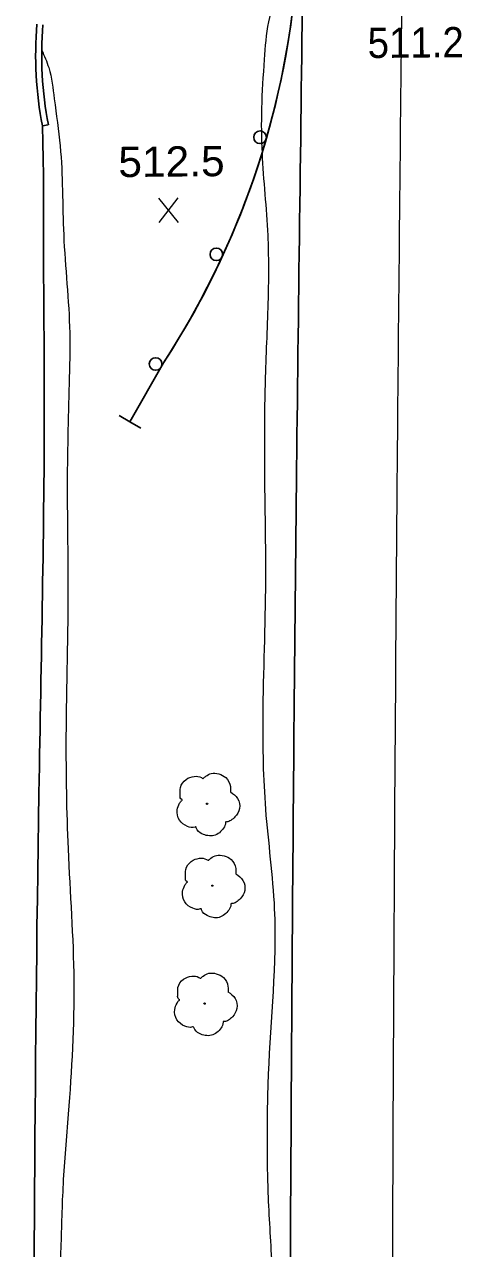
# Model space of a CAD drawing. Extents: x 2362213 to 2366494, y 6968794 to 6978110.
# Drawn here: x 2364395.3 to 2364467.4, y 6971522.8 to 6971717.1 of the extents above; entities that cross this region are included whole.
import ezdxf

# ---------------------------------------------------------------- set-up
doc = ezdxf.new("R2010")
doc.units = 0
doc.header["$LTSCALE"] = 1.9
for name, color, linetype, lineweight in [('2', 7, 'Continuous', 25), ('29', 7, 'Continuous', 13), ('31', 7, 'Continuous', 25), ('35', 7, 'Continuous', 13), ('4', 7, 'Continuous', 25), ('62', 7, 'Continuous', 13)]:
    doc.layers.add(name, color=color, linetype=linetype, lineweight=lineweight)

msp = doc.modelspace()

# ---------------------------------------------------------------- linework, layer by layer
at = {"layer": '2'}
msp.add_line((2364399.119, 6971701.216), (2364398.181, 6971701.037), dxfattribs=at)
for radius in [59.338, 58.378]:
    msp.add_arc((2364456.449, 6971712.252), radius, 175.22755, 190.89519, dxfattribs=at)
for points in [[(2364439.468, 6971722.531), (2364438.425, 6971638.877), (2364437.337, 6971472.728), (2364437.359, 6971266.609), (2364437.925, 6971121.118), (2364438.141, 6971076.417)], [(2364398.181, 6971701.037), (2364398.337, 6971694.068), (2364398.348, 6971685.648), (2364398.475, 6971661.798), (2364397.7, 6971599.308), (2364396.842, 6971464.683), (2364397.471, 6971351.284), (2364398.192, 6971207.384), (2364398.062, 6971077.095)]]:
    msp.add_spline(points, degree=3, dxfattribs=at)
at = {"layer": '29'}
for centre in [(2364424.307, 6971593.42), (2364425.141, 6971580.418), (2364423.909, 6971561.695)]:
    msp.add_circle(centre, 0.1, dxfattribs=at)
for points in [[(2364420.341, 6971593.993), (2364420.361, 6971594.003), (2364420.281, 6971594.072), (2364420.045, 6971594.7), (2364420.082, 6971595.981), (2364420.97, 6971597.279), (2364422.275, 6971597.762), (2364423.397, 6971597.572), (2364423.629, 6971597.444), (2364423.699, 6971597.445), (2364423.748, 6971597.486), (2364424.095, 6971597.779), (2364424.961, 6971598.227), (2364426.172, 6971598.159), (2364427.288, 6971597.569), (2364428.021, 6971596.146), (2364428.029, 6971595.286)], [(2364428.019, 6971595.306), (2364429.159, 6971594.247), (2364429.444, 6971592.659), (2364428.737, 6971591.332), (2364428.082, 6971590.786), (2364427.414, 6971590.569), (2364427.264, 6971590.558), (2364427.245, 6971590.448), (2364426.924, 6971589.544), (2364425.385, 6971588.38), (2364423.492, 6971588.662), (2364422.593, 6971589.603), (2364422.522, 6971589.733), (2364422.402, 6971589.711), (2364421.191, 6971589.83), (2364419.921, 6971590.828), (2364419.576, 6971592.465), (2364419.946, 6971593.489), (2364420.272, 6971593.932), (2364420.341, 6971593.983)], [(2364421.175, 6971580.99), (2364421.195, 6971581.001), (2364421.114, 6971581.07), (2364420.878, 6971581.698), (2364420.916, 6971582.978), (2364421.804, 6971584.276), (2364423.109, 6971584.759), (2364424.231, 6971584.57), (2364424.462, 6971584.442), (2364424.532, 6971584.442), (2364424.582, 6971584.483), (2364424.929, 6971584.776), (2364425.795, 6971585.225), (2364427.006, 6971585.156), (2364428.121, 6971584.567), (2364428.855, 6971583.144), (2364428.863, 6971582.284)], [(2364428.853, 6971582.304), (2364429.993, 6971581.244), (2364430.278, 6971579.657), (2364429.571, 6971578.33), (2364428.916, 6971577.784), (2364428.248, 6971577.568), (2364428.098, 6971577.556), (2364428.079, 6971577.446), (2364427.758, 6971576.543), (2364426.219, 6971575.378), (2364424.326, 6971575.66), (2364423.427, 6971576.602), (2364423.356, 6971576.731), (2364423.236, 6971576.71), (2364422.025, 6971576.828), (2364420.755, 6971577.826), (2364420.41, 6971579.463), (2364420.78, 6971580.487), (2364421.106, 6971580.93), (2364421.175, 6971580.98)], [(2364419.943, 6971562.268), (2364419.963, 6971562.278), (2364419.883, 6971562.347), (2364419.647, 6971562.975), (2364419.684, 6971564.254), (2364420.572, 6971565.553), (2364421.878, 6971566.035), (2364422.999, 6971565.846), (2364423.231, 6971565.718), (2364423.301, 6971565.719), (2364423.35, 6971565.759), (2364423.697, 6971566.053), (2364424.563, 6971566.501), (2364425.774, 6971566.432), (2364426.89, 6971565.843), (2364427.623, 6971564.42), (2364427.631, 6971563.561)], [(2364427.621, 6971563.581), (2364428.761, 6971562.522), (2364429.046, 6971560.934), (2364428.339, 6971559.608), (2364427.684, 6971559.061), (2364427.016, 6971558.845), (2364426.866, 6971558.834), (2364426.847, 6971558.723), (2364426.526, 6971557.82), (2364424.987, 6971556.656), (2364423.094, 6971556.938), (2364422.195, 6971557.879), (2364422.124, 6971558.008), (2364422.004, 6971557.987), (2364420.793, 6971558.106), (2364419.523, 6971559.104), (2364419.178, 6971560.74), (2364419.548, 6971561.764), (2364419.874, 6971562.207), (2364419.943, 6971562.258)]]:
    msp.add_spline(points, degree=3, dxfattribs=at)
at = {"layer": '31', "lineweight": 13}
for p, q in [((2364419.778, 6971685.722), (2364416.661, 6971689.572)), ((2364416.698, 6971685.692), (2364419.741, 6971689.602))]:
    msp.add_line(p, q, dxfattribs=at)
at = {"layer": '35'}
for points in [[(2364439.994, 6971733.486), (2364438.868, 6971733.036), (2364438.147, 6971731.039), (2364437.254, 6971727.13), (2364435.654, 6971722.935), (2364434.055, 6971717.589), (2364433.372, 6971711.592), (2364432.946, 6971703.848), (2364433.023, 6971696.738), (2364433.928, 6971683.656), (2364433.983, 6971673.697), (2364433.542, 6971661.142), (2364433.443, 6971643.22), (2364433.57, 6971628.801), (2364433.146, 6971607.206), (2364433.575, 6971592.568), (2364434.976, 6971576.722), (2364434.016, 6971550.531), (2364433.824, 6971541.278), (2364433.965, 6971531.67), (2364434.542, 6971520.444), (2364434.682, 6971512.086), (2364434.675, 6971506.476), (2364435.314, 6971502.38), (2364436.137, 6971497.868), (2364436.783, 6971490.985), (2364437.739, 6971484.064), (2364438.525, 6971479.27), (2364439.8, 6971472.402), (2364440.687, 6971465.411), (2364441.495, 6971461.388), (2364443.097, 6971457.012), (2364444.712, 6971452.268), (2364445.855, 6971447.699), (2364447.271, 6971444.003), (2364449.509, 6971437.943), (2364450.884, 6971434.246), (2364453.185, 6971427.897), (2364454.981, 6971422.025), (2364456.956, 6971413.122), (2364458.617, 6971405.588), (2364460.577, 6971396.157), (2364461.604, 6971390.206), (2364462.553, 6971379.734), (2364463.261, 6971367.35), (2364463.76, 6971358.005), (2364464.421, 6971351.682), (2364465.168, 6971338.327), (2364465.763, 6971318.912), (2364466.44, 6971301.388), (2364467.187, 6971290.084), (2364468.006, 6971276.621), (2364468.769, 6971265.798), (2364469.742, 6971250.727), (2364469.962, 6971234.958), (2364470.265, 6971224.151), (2364470.975, 6971209.477), (2364470.852, 6971201.435), (2364471.097, 6971179.917), (2364471.587, 6971168.311), (2364471.9, 6971157.543), (2364471.893, 6971141.392), (2364472.246, 6971129.575), (2364472.023, 6971115.212), (2364473.192, 6971076.392)], [(2364398.076, 6971713.086), (2364399.183, 6971710.297), (2364400.06, 6971705.325), (2364401.001, 6971697.854), (2364401.556, 6971683.768), (2364402.514, 6971668.177), (2364402.421, 6971660.105), (2364402.121, 6971643.302), (2364402.232, 6971628.432), (2364401.925, 6971604.038), (2364402.254, 6971586.24), (2364403.164, 6971565.257), (2364402.275, 6971544.118), (2364401.461, 6971533.07), (2364401.098, 6971522.856), (2364400.726, 6971512.523), (2364400.206, 6971504.086), (2364399.05, 6971497.435), (2364397.63, 6971492.192), (2364396.332, 6971485.659), (2364395.377, 6971479.839), (2364394.306, 6971472.559), (2364393.312, 6971465.63), (2364392.265, 6971460.129), (2364390.48, 6971453.261), (2364387.528, 6971447.194), (2364384.888, 6971440.878), (2364382.597, 6971433.535), (2364381.192, 6971425.752), (2364379.492, 6971415.155), (2364378.08, 6971403.881), (2364377.087, 6971393.651), (2364376.513, 6971384.645), (2364375.769, 6971372.459), (2364375.135, 6971361.341), (2364373.979, 6971348.249), (2364373.049, 6971336.76), (2364372.148, 6971319.971), (2364371.677, 6971303.315), (2364371.199, 6971287.35), (2364370.704, 6971265.854), (2364370.685, 6971234.243), (2364370.682, 6971205.071), (2364370.568, 6971192.929), (2364369.646, 6971173.19), (2364369.11, 6971161.165), (2364368.524, 6971146.137), (2364367.858, 6971133.071), (2364367.245, 6971119.765), (2364366.961, 6971104.45), (2364366.737, 6971088.069), (2364366.639, 6971077.416)]]:
    msp.add_spline(points, degree=3, dxfattribs=at)
at = {"layer": '4'}
msp.add_line((2364412.079, 6971654.047), (2364417.4, 6971663.448), dxfattribs=at)
for points in [[(2364412.079, 6971654.047), (2364417.4, 6971663.448), (2364418.651, 6971665.39), (2364419.853, 6971667.362), (2364421.024, 6971669.343), (2364422.185, 6971671.354), (2364423.285, 6971673.385), (2364424.346, 6971675.425), (2364425.396, 6971677.495), (2364426.387, 6971679.574), (2364427.347, 6971681.674), (2364428.276, 6971683.803), (2364429.156, 6971685.921), (2364430.016, 6971688.069), (2364430.836, 6971690.237), (2364431.595, 6971692.405), (2364432.334, 6971694.592), (2364433.033, 6971696.789), (2364433.702, 6971699.015), (2364434.321, 6971701.231), (2364434.899, 6971703.476), (2364435.448, 6971705.712), (2364435.957, 6971707.967), (2364436.415, 6971710.231), (2364436.834, 6971712.495), (2364437.232, 6971714.769), (2364437.57, 6971717.063), (2364437.878, 6971719.356)], [(2364413.799, 6971653.033), (2364412.079, 6971654.047), (2364410.359, 6971655.061)]]:
    msp.add_lwpolyline(points, dxfattribs=at)
for centre in [(2364432.72, 6971699.233), (2364425.778, 6971680.645), (2364416.134, 6971663.242)]:
    msp.add_circle(centre, 1, dxfattribs=at)
msp.add_arc((2364306.573, 6971735.752), 132.327, 326.87941, 355.16178, dxfattribs=at)
at = {"layer": '62'}
msp.add_spline([(2364454.416, 6971077.102), (2364453.943, 6971229.665), (2364453.589, 6971434.881), (2364454.513, 6971647.621), (2364456.121, 6971796.873), (2364457.995, 6971943.447)], degree=3, dxfattribs=at)

# ---------------------------------------------------------------- texts
at = {"layer": '31'}
for s, width, p in [('511.2', 0.95, (2364449.801, 6971711.809)), ('512.5', 1.05, (2364410.249, 6971692.911))]:
    msp.add_text(s, height=4.8, rotation=0.546, dxfattribs=dict(at, width=width)).set_placement(p)

doc.saveas('drawing.dxf')
